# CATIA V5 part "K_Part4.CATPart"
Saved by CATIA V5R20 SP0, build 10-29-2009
Part number: glissiere_roue_gauche
Publications: "Corps principal", "largeur de la glissière", "Point.1", "Point.2", "Point.3", "Point.4", "Droite.1", "Droite.2", "Droite.3", "Droite.4", "Droite.5"
Bounding box of the stored display mesh (mm): x -50 to 50, y 400 to 500, z 0 to 0
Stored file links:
  G:\Khaled_CFAO_2011\ST2M\ST2M_GR1\cdurantin\cdurantin\Khaled\CAD_ThinkMOTION\K_Part4.CATPart
  G:\Khaled_CFAO_2011\ST2M\ST2M_GR1\cdurantin\cdurantin\Khaled\CAD_ThinkMOTION\K_Corps.CATPart
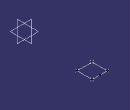
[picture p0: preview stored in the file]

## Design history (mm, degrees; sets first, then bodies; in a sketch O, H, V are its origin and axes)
Parameters
  `largeur de la glissière` = 100 mm
External parameters (linked from other documents)
  `External.Ecart entre les barres du corps` = 100 mm
  `External.Longueur de barres du corps` = 800 mm
Body1 (main body)
  Point1: type OnPlane, Support xy-plane, H 50 {= `External.Ecart entre les barres du corps` /2}, V 400 {= `External.Longueur de barres du corps` /2}, Direction (1, 0, 0)
  Point2: type OnPlane, Support xy-plane, H -50 {= -`External.Ecart entre les barres du corps` /2}, V 400 {= `External.Longueur de barres du corps` /2}, Direction (1, 0, 0)
  Point3: type OnPlane, Support xy-plane, H 50 {= `External.Ecart entre les barres du corps` /2}, V 500 {= `External.Longueur de barres du corps` /2+`largeur de la glissière`}, Direction (1, 0, 0)
  Point4: type OnPlane, Support xy-plane, H -50 {= -`External.Ecart entre les barres du corps` /2}, V 500 {= `External.Longueur de barres du corps` /2+`largeur de la glissière`}, Direction (1, 0, 0)
  Line1: type PtPt, FirstPoint Point2, SecondPoint Point1
  Line2: type PtPt, FirstPoint Point2, SecondPoint Point4
  Line3: type PtPt, FirstPoint Point1, SecondPoint Point3
  Line4: type PtDir, RefPoint Point4, Direction yz-plane, Start 0, End 50
  Line5: type PtDir, RefPoint Point3, Direction yz-plane, Start 0, End -50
